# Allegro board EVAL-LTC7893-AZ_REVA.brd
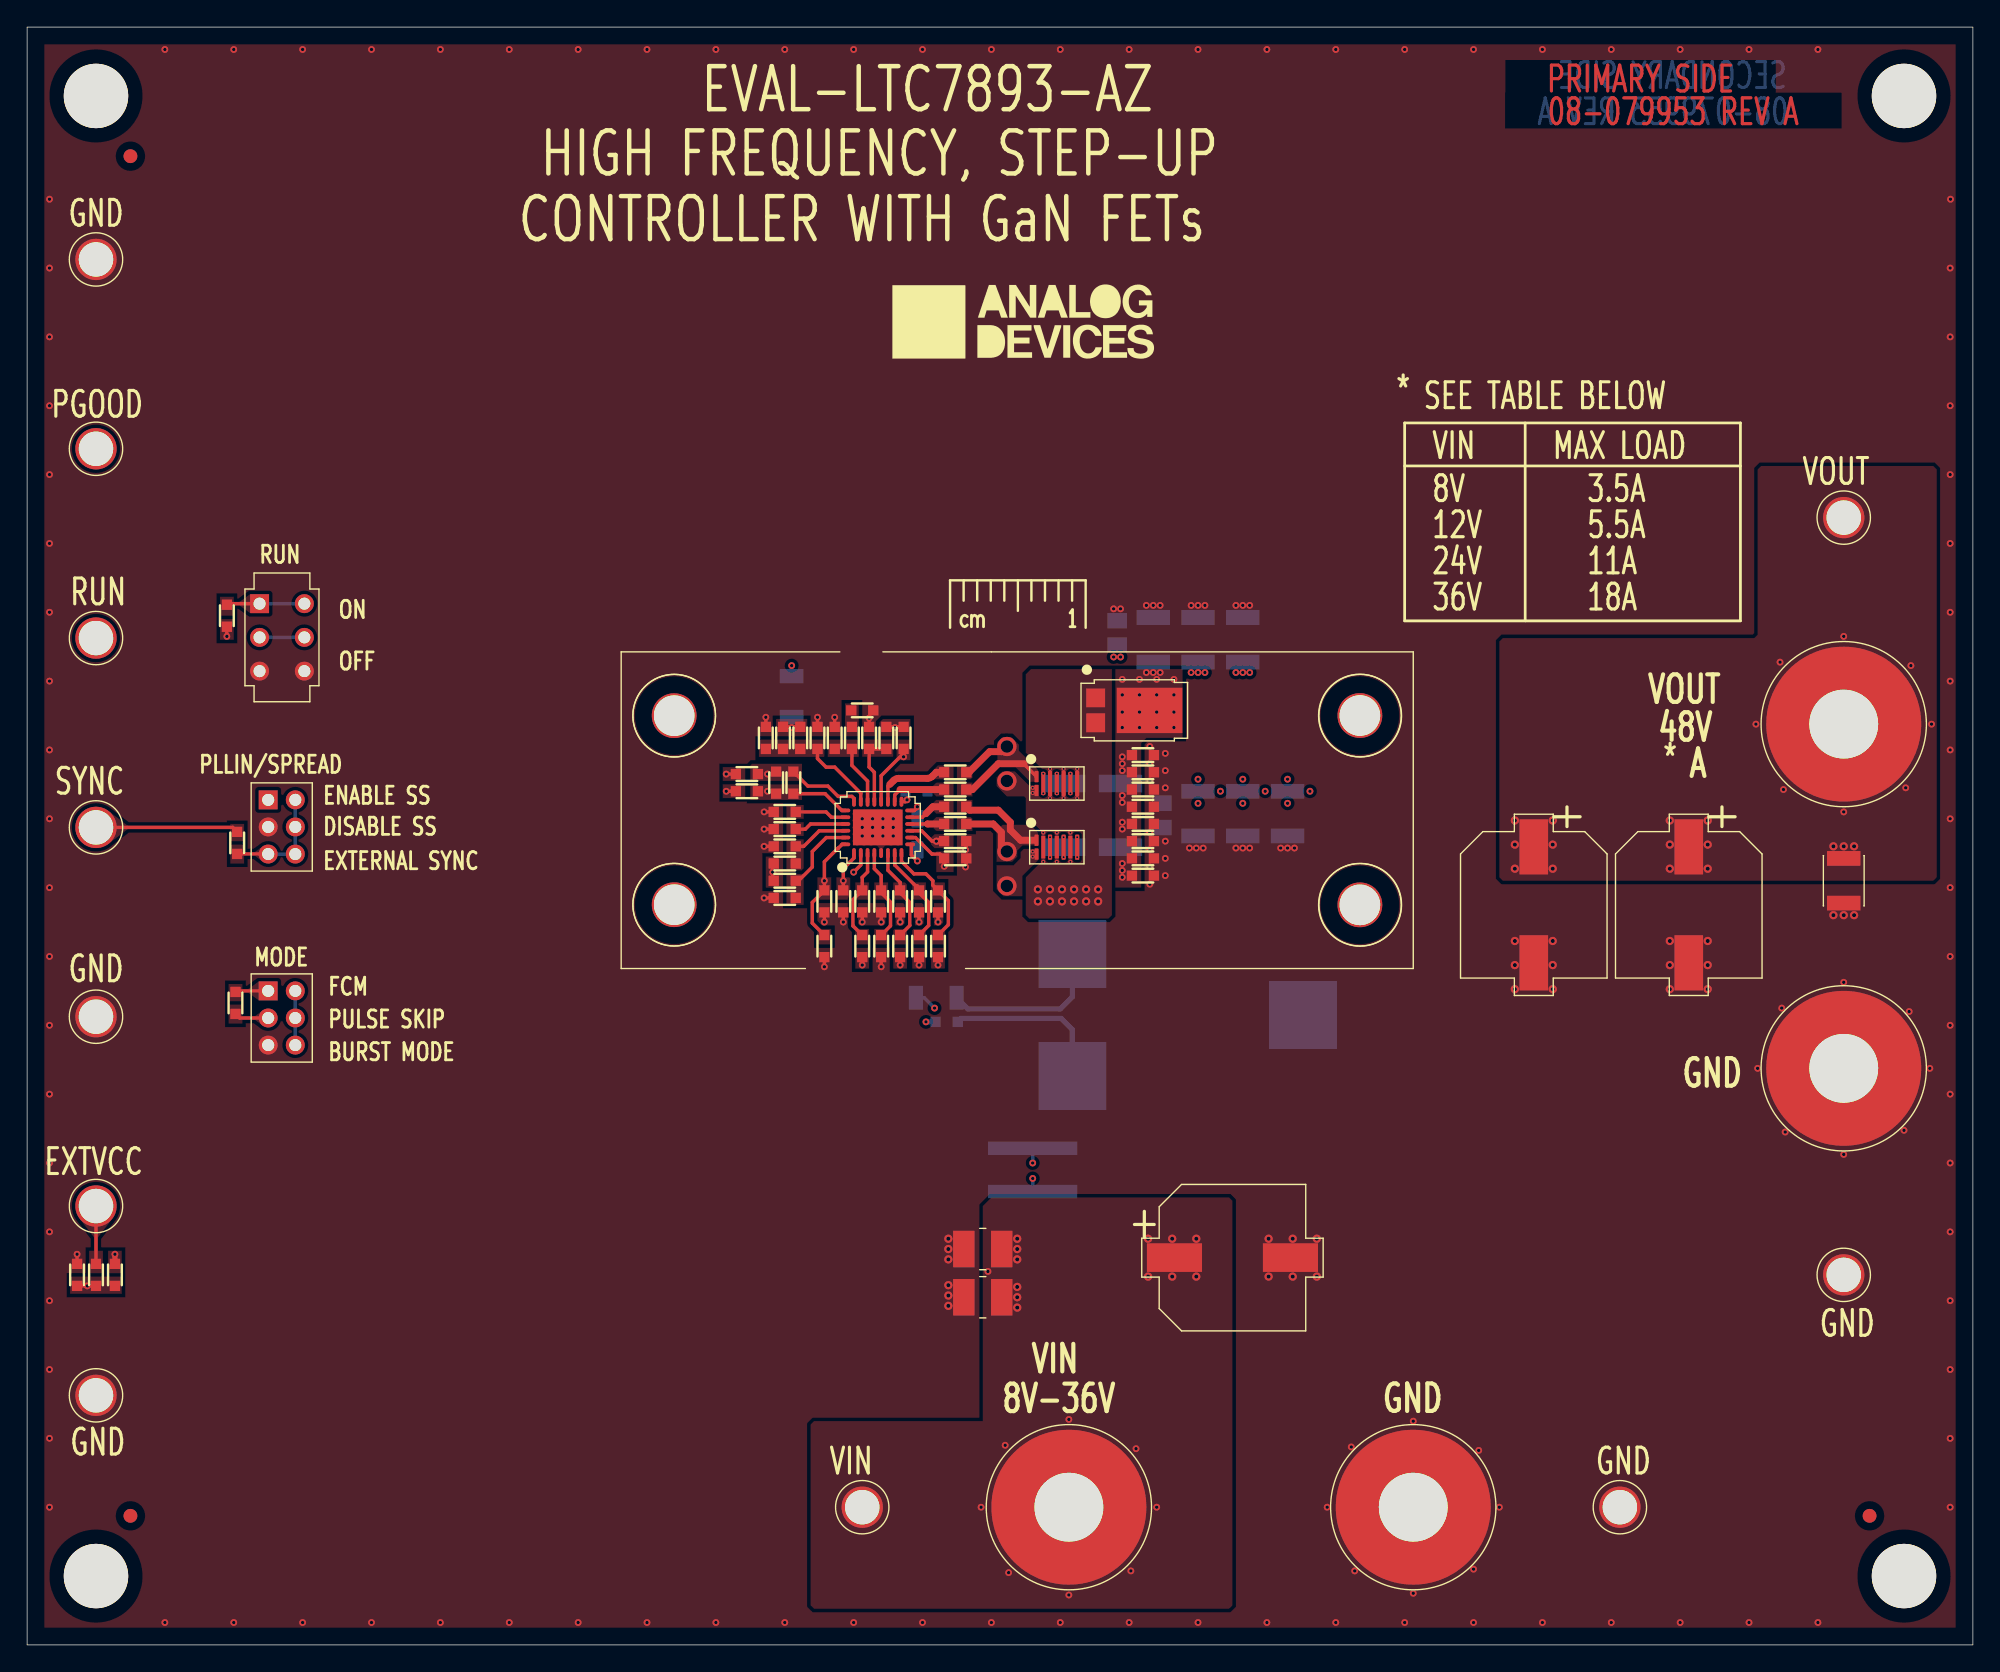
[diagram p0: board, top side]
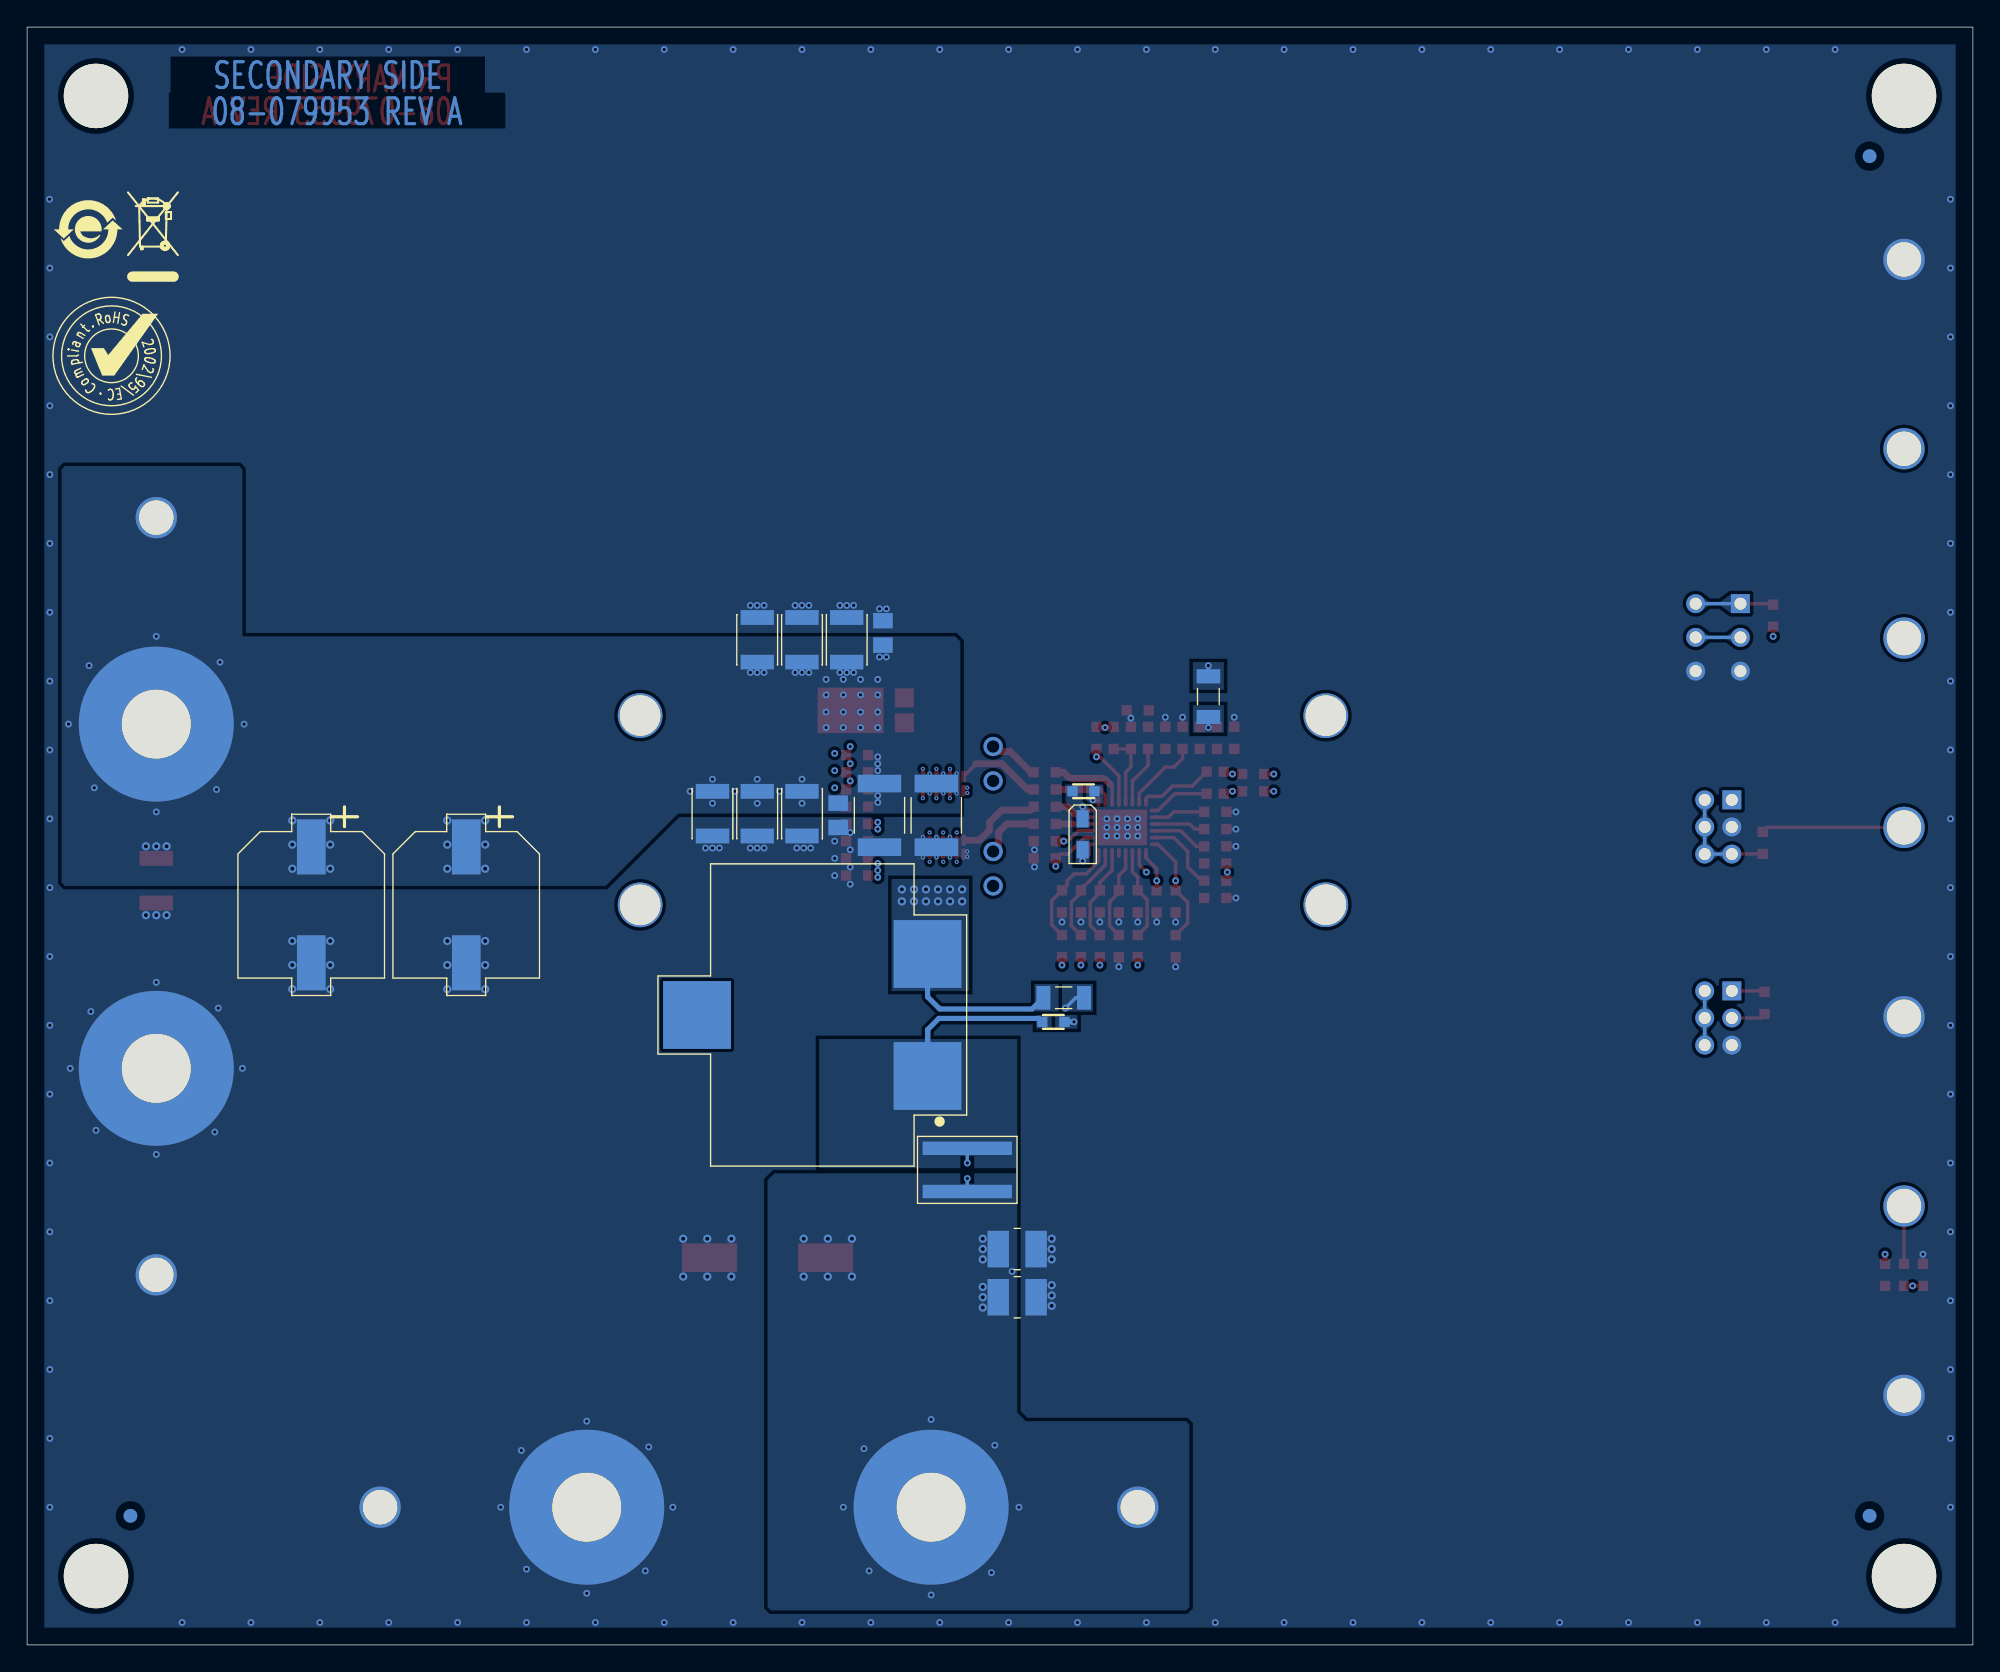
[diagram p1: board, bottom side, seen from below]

Outline 143.51 x 119.38 mm; copper layers: TOP, LAYER_2, LAYER_3, LAYER_4, LAYER_5, BOTTOM. Coordinates in mm from the lower left corner of the outline.
Outline path: 0,119.38 0,0 143.51,0 143.51,119.38 0,119.38

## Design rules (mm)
constraint set DEFAULT: min track width 0.254

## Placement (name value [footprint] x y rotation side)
C1  TBD0603  [C0603]  57.02 66.93 270 top
C2  TBD0603  [C0603]  58.29 66.93 90 top
C3  TBD0603  [C0603]  60.2 54.86 270 top
C4  0.022uF  [C0603]  60.83 66.93 90 top
C5  0.1uF  [C0603]  62.99 54.86 270 top
C6  220pF  [C0603]  59.56 66.93 90 top
C7  0.1uF  [C0603]  65.79 54.86 270 top
C8  100PF  [C0603]  58.8 54.86 270 top
C9  1uF  [C0603]  68.45 58.04 0 top
C10  0.1uF  [C0603]  67.18 54.86 270 top
C11  4.7UF  [C0603]  68.45 59.31 0 top
C12  0.01uF  [C0603]  56.52 63.63 90 top
C13  0.1uF  [C0603]  65.6 62.99 180 bottom
C14  4.7UF  [C1812H110]  80.64 61.21 270 bottom
C15  4.7UF  [C1812H110]  76.45 61.21 270 bottom
C16  4.7uF  [C1210H87]  89.66 74.17 90 bottom
C17  4.7uF  [C1210H87]  86.36 74.17 90 bottom
C18  100UF  [CPLSMSQ406H508]  111.12 54.61 270 top
C19  100UF  [CPLSMSQ406H508]  122.56 54.61 270 top
C20  1UF  [C0805H55]  80.39 74.68 90 bottom
C21  1UF  [C0805H55]  83.69 61.21 270 bottom
C22  4.7uF  [C1210H87]  83.06 74.17 90 bottom
C23  4.7uF  [C1210H87]  92.96 61.34 270 bottom
C24  4.7uF  [C1210H87]  86.36 61.34 270 bottom
C25  4.7uF  [C1210H87]  89.66 61.34 270 bottom
C26  10uF  [C1210-2]  70.48 25.65 180 top
C27  4.7uF  [C1210H87]  133.99 56.39 270 top
C28  100UF  [CPLSMSQ406H508]  111.12 54.61 270 bottom
C29  10uF  [C1210-2]  70.48 29.21 180 top
C30  10uF  [C1210-2]  70.48 29.21 180 bottom
C31  10uF  [C1210-2]  70.48 25.65 180 bottom
C32  100UF  [CPLSMSQ406H508]  122.56 54.61 270 bottom
C33  100UF  [CPLSMSQ406H508]  88.9 28.57 0 top
C34  0.22UF  [C0603]  82.3 65.66 0 top
C35  0.22UF  [C0603]  82.3 64.39 0 top
C36  0.22UF  [C0603]  82.3 63.12 0 top
C37  0.22UF  [C0603]  82.3 61.85 0 top
C38  0.22UF  [C0603]  82.3 60.58 0 top
C39  0.22UF  [C0603]  82.3 59.31 0 top
C40  0.22UF  [C0603]  82.3 58.04 0 top
C41  0.22UF  [C0603]  82.3 56.77 0 top
D1  BAT42WS-7-F  [SOD323]  65.66 59.82 270 bottom
D2  MBR5U100-TP  [TO227]  81.66 68.96 0 top
J1  CKFH1032-10  [CNCFCKFH1032-10]  76.83 10.16 0 top
J2  CKFH1032-10  [CNCFCKFH1032-10]  102.23 10.16 0 top
J3  CKFH1032-10  [CNCFCKFH1032-10]  133.99 67.94 0 top
J4  CKFH1032-10  [CNCFCKFH1032-10]  133.99 42.55 0 top
JP1  62000621121  [CNTHMHDR2X3L236W157H248]  17.78 48.26 270 top
JP2  62000621121  [CNTHMHDR2X3L236W157H248]  17.78 62.36 270 top
L1  3.1UH  [LSML858W571H571]  85.6 46.48 90 bottom
NOREF  -  []  -76.2 -76.2 0 top
NOREF#2  -  []  -76.2 -76.2 0 top
NOREF#3  VAL  []  73.03 61.59 0 top
NOREF#4  -  []  238.7 41.21 0 top
NOREF#5  -  []  124.26 115.57 270 top
NOREF#6  -  []  0 119.38 0 top
NOREF#7  -  [unnamed#2]  138.43 114.3 180 top
NOREF#8  -  [unnamed#2]  7.62 109.86 0 top
NOREF#9  -  []  68.07 75.06 0 top
NOREF#10  -  [unnamed#2]  5.08 5.08 180 top
NOREF#11  -  []  63.5 0 90 top
NOREF#12  -  []  -222.25 -146.05 0 top
NOREF#13  -  [unnamed#2]  5.08 114.3 180 top
NOREF#14  -  []  73.41 96.27 0 top
NOREF#15  -  [unnamed#2]  135.89 9.53 0 top
NOREF#16  -  []  143.51 0 90 top
NOREF#17  -  []  244.35 286 0 top
NOREF#18  -  [unnamed#2]  7.62 9.53 0 top
NOREF#19  -  []  78.8 71.12 0 top
NOREF#20  -  []  249.05 252.09 0 top
NOREF#21  -  []  -76.2 -76.2 0 top
NOREF#22  -  []  0 63.5 270 top
NOREF#23  -  []  294.96 220.28 0 top
NOREF#24  -  []  76.2 125.73 0 top
NOREF#25  -  [unnamed#2]  138.43 5.08 180 top
NOREF#26  -  []  -222.25 -146.05 0 top
NOREF#27  -  []  0 0 0 top
NOREF#28  -  []  63.5 63.5 180 top
NOREF#29  -  []  269.18 136.97 0 top
NOREF#30  -  []  134.43 100.65 180 bottom
NOREF#31  -  [unnamed#2]  7.62 109.86 180 bottom
NOREF#32  -  []  137.29 95.12 180 bottom
NOREF#33  -  [unnamed#2]  7.62 9.53 180 bottom
NOREF#34  -  []  139 104.46 180 bottom
NOREF#35  -  [unnamed#2]  135.89 9.53 180 bottom
P1  9774010243R  [CNWURTH9774010243R]  47.73 68.57 0 top
P2  9774010243R  [CNWURTH9774010243R]  47.73 54.62 0 top
P3  9774010243R  [CNWURTH9774010243R]  98.3 68.58 0 top
P4  9774010243R  [CNWURTH9774010243R]  98.3 54.61 0 top
Q1  EPC2088  [DIE8_3_5X1_95_A]  75.95 63.56 0 top
Q2  EPC2088  [DIE8_3_5X1_95_A]  75.95 58.86 0 top
R1  475K  [R0603]  55.75 66.93 270 top
R2  12.1K  [R0603]  54.48 66.93 90 top
R3  1K  [R0603]  15.49 59.18 270 top
R4  TBD0603  [R0603]  5.08 27.3 270 top
R5  TBD0603  [R0603]  62.99 51.56 270 top
R6  0  [R0603]  3.68 27.3 90 top
R7  10K  [R0603]  61.59 68.96 0 top
R8  1MEG  [R0603]  14.73 75.95 90 top
R9  1MEG  [R0603]  64.64 66.93 270 top
R10  100K  [R0603]  15.37 47.37 270 top
R11  187K  [R0603]  58.8 51.56 270 top
R12  TBD0603  [R0603]  61.59 51.56 90 top
R13  73.2K  [R0603]  61.59 54.86 90 top
R14  0  [R0603]  65.79 51.56 90 top
R15  0  [R0603]  63.37 66.93 270 top
R16  TBD0603  [R0603]  62.1 66.93 270 top
R17  TBD0603  [R0603]  55.88 57.66 0 top
R18  0  [R0603]  55.88 58.93 180 top
R19  0  [R0603]  67.18 51.56 90 top
R20  1  [R0603]  68.45 64.39 0 top
R21  1  [R0603]  68.45 63.12 0 top
R22  2.2  [R0603]  68.45 60.58 0 top
R23  1  [R0603]  68.45 61.85 0 top
R24  24.9K  [R0603]  55.88 60.2 180 top
R25  10K  [R0603]  55.88 61.47 180 top
R26  TBD0603  [R0603]  64.39 51.56 270 top
R27  TBD0603  [R0603]  64.39 54.86 270 top
R28  TBD0603  [R0603]  55.24 63.63 90 top
R29  TBD0603  [R0603]  55.88 56.39 180 top
R30  TBD0603  [R0603]  55.88 55.12 180 top
R31  TBD1206  [R1206]  67.06 47.75 180 bottom
R32  TBD0603  [R0603]  67.82 45.97 180 bottom
R33  1  [R0603]  53.09 64.26 0 top
R34  0.002  [R1225H28]  74.17 35.05 270 bottom
R35  TBD0603  [R0603]  6.48 27.3 90 top
R36  0  [R0603]  53.09 62.99 0 top
R37  10  [R1206]  56.39 69.98 90 bottom
S1  JS202011CQN  [SWTHL354W142H217]  17.14 76.83 270 top
TP1  2501-2-00-80-00-00-07-0  [CNMILLMAX2501]  5.08 74.3 0 top
TP2  2501-2-00-80-00-00-07-0  [CNMILLMAX2501]  5.08 88.27 0 top
TP3  2501-2-00-80-00-00-07-0  [CNMILLMAX2501]  5.08 60.33 0 top
TP4  2501-2-00-80-00-00-07-0  [CNMILLMAX2501]  5.08 32.38 0 top
TP5  2501-2-00-80-00-00-07-0  [CNMILLMAX2501]  5.08 46.35 0 top
TP6  2501-2-00-80-00-00-07-0  [CNMILLMAX2501]  5.08 102.23 0 top
TP7  2501-2-00-80-00-00-07-0  [CNMILLMAX2501]  133.99 83.19 0 top
TP10  2501-2-00-80-00-00-07-0  [CNMILLMAX2501]  133.99 27.3 0 top
TP11  2501-2-00-80-00-00-07-0  [CNMILLMAX2501]  61.59 10.16 0 top
TP14  2501-2-00-80-00-00-07-0  [CNMILLMAX2501]  117.47 10.16 0 top
TP15  2501-2-00-80-00-00-07-0  [CNMILLMAX2501]  5.08 18.41 0 top
U1  LTC7893AUFDM#PBF  [QFN28_5X4_PAD3_65X2_65_05-08-1682]  62.74 60.33 0 top

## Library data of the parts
C1-C3 = CAP: User Part Number: UPN; alternate symbols: (C0603); part number: CAP_SM-TBD0603,TBD0603,TBD0603,E000382,C0603
C4 = CAP: Tolerance: 10; User Part Number: UPN; alternate symbols: (C0603); part number: CAP_SM-0.022UF,50V,10,E015725,C0603; tolerance: 10
C5 C10 C13 = CAP: Tolerance: 10; User Part Number: UPN; alternate symbols: (C0603); part number: CAP_SM-0.1UF,25V,10,E013746,C0603; tolerance: 10
C6 = CAP: Tolerance: 5; User Part Number: UPN; alternate symbols: (C0603); part number: CAP_SM-220PF,50V,5,E000417,C0603; tolerance: 5
C7 = CAP: Tolerance: 10; User Part Number: UPN; alternate symbols: (C0603); part number: CAP_SM-0.1UF,100V,10,E024908,C0603; tolerance: 10
C8 = CAP: Tolerance: 10; User Part Number: UPN; alternate symbols: (C0603); part number: CAP_SM-100PF,25V,10,E062855,C0603; tolerance: 10
C9 = CAP: Tolerance: 10; User Part Number: UPN; alternate symbols: (C0603); part number: CAP_SM-1UF,25V,10,E033832,C0603; tolerance: 10
C11 = CAP: Tolerance: 10; User Part Number: UPN; alternate symbols: (C0603); part number: CAP_SM-4.7UF,25V,10,E058970,C0603; tolerance: 10
C12 = CAP: Tolerance: 10; User Part Number: UPN; alternate symbols: (C0603); part number: CAP_SM-0.01UF,50V,10,E018587,C0603; tolerance: 10
C14 C15 = CAP: User Part Number: UPN; Tolerance: 10; alternate symbols: (C1812H110); part number: CAP_SM-4.7UF,100V,10,E063338,C1812H110; tolerance: 10
C16 C17 C22-C25 C27 = CAP: Tolerance: 10; User Part Number: UPN; alternate symbols: (C1210H87); part number: CAP_SM-4.7UF,100V,10,E033812,C1210H87; tolerance: 10
C18 C19 C28 C32 C33 = CAPP: User Part Number: UPN; Tolerance: 20; alternate symbols: (CPLSMSQ406H508); part number: CAPP_SM-100UF,63V,20,E067384,CPLSMSQ406H508; tolerance: 20
C20 C21 = CAP: User Part Number: UPN; Tolerance: 10; alternate symbols: (C0805H55); part number: CAP_SM-1UF,100V,10,E048499,C0805H55; tolerance: 10
C26 C29-C31 = CAP: Tolerance: 10; User Part Number: UPN; alternate symbols: (C1210-2); part number: CAP_SM-10UF,50V,10,E022361,C1210-2; tolerance: 10
C34-C41 = CAP: Tolerance: 10; User Part Number: UPN; alternate symbols: (C0603); part number: CAP_SM-0.22UF,100V,10,E061685,C0603; tolerance: 10
D1 = DIOSCHOTTKY: Tolerance: N/A; User Part Number: UPN; alternate symbols: (SOD323); part number: DIOSCHOTTKY_SM-BAT42WS-7-F,30V,N/A,E033361,SOD323; tolerance: N/A
D2 = DIOSCHOTTKY_3P: User Part Number: UPN; Tolerance: N/A; alternate symbols: (TO227); part number: DIOSCHOTTKY_3P_SM-MBR5U100-TP,100V,N/A,E067592,TO227; tolerance: N/A
J1-J4 = CNTP1P: Tolerance: N/A; User Part Number: UPN; alternate symbols: (CNCFCKFH1032-10_C450D200); part number: CNTP1P_TH-CKFH1032-10,E050511,CNCFCKFH1032-10; tolerance: N/A
JP1 JP2 = CN6P_ODD_EVEN: User Part Number: UPN; Tolerance: N/A; alternate symbols: (CNTHMHDR2X3L236W157H248); part number: CN6P_ODD_EVEN_SM-62000621121,E035206,CNTHMHDR2X3L236W157H248; tolerance: N/A
L1 = IND: Tolerance: 15; User Part Number: UPN; alternate symbols: (LSML858W571H571); part number: IND_SM-3.1UH,15,E067382,LSML858W571H571; tolerance: 15
NOREF#3 = -: User Part Number: UPN; Tolerance: TOL
P1-P4 = CN1P: Tolerance: N/A; User Part Number: UPN; alternate symbols: (CNWURTH9774010243R); part number: CN1P_TH-9774010243R,E060235,CNWURTH9774010243R; tolerance: N/A
Q1 Q2 = TRANNGANFET8P: Tolerance: www.epc-co.com; User Part Number: UPN; alternate symbols: (DIE8_3_5X1_95_A); part number: TRANNGANFET8P_SM-EPC2088,E063004,DIE8_3_5X1_95_A; tolerance: www.epc-co.com
R1 = RES: Tolerance: 1; User Part Number: UPN; alternate symbols: (R0603); part number: RES_SM-475K,E032846,1/10W,1,R0603; tolerance: 1
R2 = RES: Tolerance: 1; User Part Number: UPN; alternate symbols: (R0603); part number: RES_SM-12.1K,E003741,1/10W,1,R0603; tolerance: 1
R3 = RES: Tolerance: 1; User Part Number: UPN; alternate symbols: (R0603); part number: RES_SM-1K,E003678,1/10W,1,R0603; tolerance: 1
R4 R5 R12 R16 R17 R26-R30 R32 R35 = RES: User Part Number: UPN; alternate symbols: (R0603); part number: RES_SM-TBD0603,E004050,TBD0603,TBD0603,R0603
R6 R14 R15 R18 R19 R36 = RES: Tolerance: JUMPER; User Part Number: UPN; alternate symbols: (R0603); part number: RES_SM-0,E006826,1/10W,JUMPER,R0603; tolerance: JUMPER
R7 R25 = RES: Tolerance: 1; User Part Number: UPN; alternate symbols: (R0603); part number: RES_SM-10K,E003671,1/10W,1,R0603; tolerance: 1
R8 R9 = RES: Tolerance: 1; User Part Number: UPN; alternate symbols: (R0603); part number: RES_SM-1MEG,E003682,1/10W,1,R0603; tolerance: 1
R10 = RES: Tolerance: 1; User Part Number: UPN; alternate symbols: (R0603); part number: RES_SM-100K,E010279,1/10W,1,R0603; tolerance: 1
R11 = RES: Tolerance: 1; User Part Number: UPN; alternate symbols: (R0603); part number: RES_SM-187K,E057319,1/10W,1,R0603; tolerance: 1
R13 = RES: Tolerance: 1; User Part Number: UPN; alternate symbols: (R0603); part number: RES_SM-73.2K,E043106,1/10W,1,R0603; tolerance: 1
R20 R21 R23 R33 = RES: User Part Number: UPN; alternate symbols: (R0603); part number: RES_SM-1,E044403,1/10W,1,R0603
R22 = RES: Tolerance: 1; User Part Number: UPN; alternate symbols: (R0603); part number: RES_SM-2.2,E017481,1/10W,1,R0603; tolerance: 1
R24 = RES: Tolerance: 1; User Part Number: UPN; alternate symbols: (R0603); part number: RES_SM-24.9K,E030453,1/10W,1,R0603; tolerance: 1
R31 = RES: User Part Number: UPN; alternate symbols: (R1206); part number: RES_SM-TBD1206,E004052,TBD1206,TBD1206,R1206
R34 = RES: User Part Number: UPN; Tolerance: 2; alternate symbols: (R1225H28); part number: RES_SM-0.002,E046965,3W,2,R1225H28; tolerance: 2
R37 = RES: User Part Number: UPN; Tolerance: 1; alternate symbols: (R1206); part number: RES_SM-10,E003286,1/4W,1,R1206; tolerance: 1
S1 = SWDPDT_V5: Tolerance: N/A; User Part Number: UPN; alternate symbols: (SWTHL354W142H217); part number: SWDPDT_V5_TH-JS202011CQN,E025828,SWTHL354W142H217; tolerance: N/A
TP1-TP7 TP10 TP11 TP14 TP15 = CNTP1P: User Part Number: UPN; Tolerance: N/A; alternate symbols: (CNMILLMAX2501); part number: CNTP1P_TH-2501-2-00-80-00-00-07-0,E031108,CNMILLMAX2501; tolerance: N/A
U1 = ADILTC7893: User Part Number: UPN; Tolerance: N/A; alternate symbols: (QFN28_5X4_PAD3_65X2_65_05-08-1682); part number: ADILTC7893_SM-LTC7893AUFDM#PBF,E062848,QFN28_5X4_PAD3_65X2_65_05-08-1682; tolerance: N/A

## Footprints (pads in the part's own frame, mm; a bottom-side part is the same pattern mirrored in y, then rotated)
C0603
  rect 0.762x0.762 smd: 1(-0.813,0) 2(0.813,0)
C0805H55
  rect 1.143x1.448 smd: 1(-0.9,0) 2(0.9,0)
C1210-2
  rect 1.575x2.692 smd: 1(-1.397,0) 2(1.397,0)
C1210H87
  rect 1.092x2.464 smd: 1(-1.646,0) 2(1.646,0)
C1812H110
  rect 1.295x3.2 smd: 1(-2.348,0) 2(2.348,0)
CNCFCKFH1032-10
  round 11.43 hole 5.08: 1(0,0)
CNMILLMAX2501
  round 3.048 hole 2.54: 1(0,0)
CNTHMHDR2X3L236W157H248
  rect 1.397x1.397 hole 0.889: 1(0,0)
  round 1.397 hole 0.889: 2(0,2) 3(2,0) 4(2,2) 5(4,0) 6(4,2)
CNWURTH9774010243R
  round 3.302 hole 2.997 unplated: (0,0)
  round 0 smd: 1(0,0)
CPLSMSQ406H508
  rect 4.064x2.108 smd: N(4.277,0) P(-4.277,0)
DIE8_3_5X1_95_A
  rrect 0.305x0.838 smd: 1(-1.5,0.513) 2(-1.5,-0.513)
  rrect 0.305x1.676 smd: 3(-1,0) 5(0,0) 7(1,0)
  rrect 0.305x1.854 smd: 4(-0.5,0) 6(0.5,0) 8(1.5,0)
LSML858W571H571
  rect 5.004x5.004 smd: (0,8.502) 1(-4.502,-8.502) 2(4.502,-8.502)
QFN28_5X4_PAD3_65X2_65_05-08-1682
  oval 0.279x0.737 smd: 1(-1.75,-1.893) 2(-1.25,-1.893) 3(-0.75,-1.893) 4(-0.25,-1.893) 5(0.25,-1.893) 6(0.75,-1.893) 7(1.25,-1.893) 8(1.75,-1.893) 15(1.75,1.893) 16(1.25,1.893) 17(0.75,1.893) 18(0.25,1.893) 19(-0.25,1.893) 20(-0.75,1.893) 21(-1.25,1.893) 22(-1.75,1.893)
  oval 0.737x0.279 smd: 9(2.393,-1.25) 10(2.393,-0.75) 11(2.393,-0.25) 12(2.393,0.25) 13(2.393,0.75) 14(2.393,1.25) 23(-2.393,1.25) 24(-2.393,0.75) 25(-2.393,0.25) 26(-2.393,-0.25) 27(-2.393,-0.75) 28(-2.393,-1.25)
  rect 3.658x2.642 smd: 29(0,0)
R0603
  rect 0.762x0.762 smd: 1(-0.813,0) 2(0.813,0)
R1206
  rect 1.041x1.753 smd: 1(-1.5,0) 2(1.5,0)
R1225H28
  rect 0.991x6.579 smd: 1(-1.595,0) 2(1.595,0)
SOD323
  rect 1.27x0.889 smd: A(1.143,0) C(-1.143,0)
SWTHL354W142H217
  rect 1.397x1.397 hole 0.889: 1(0,0)
  round 1.397 hole 0.889: 2(2.489,0) 3(4.978,0) 4(0,3.302) 5(2.489,3.302) 6(4.978,3.302)
TO227
  rect 1.397x1.397 smd: 1(-2.851,0.92) 2(-2.851,-0.92)
  rect 4.851x3.353 smd: 3(1.123,0)
unnamed#2
  round 4.75 hole 4.75 unplated: (0,0)

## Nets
GND_SIGNAL: C2.2(N2) C3.2(N2) C5.2(N2) C6.2(N2) C7.2(N2) C8.2(N2) C9.2(N2) C10.2(N2) C11.2(N2) C14.2(N2) C15.2(N2) C16.2(N2) C17.2(N2) C18.N(N2) C19.N(N2) C20.2(N2) C21.2(N2) C22.2(N2) C23.2(N2) C24.2(N2) C25.2(N2) C26.2(N2) C27.2(N2) C28.N(N2) C29.2(N2) C30.2(N2) C31.2(N2) C32.N(N2) C33.N(N2) C34.2(N2) C35.2(N2) C36.2(N2) C37.2(N2) C38.2(N2) C39.2(N2) C40.2(N2) C41.2(N2) J2.1(N1) J4.1(N1) JP1.5 JP2.3 Q2.2 Q2.4 Q2.6 Q2.8(S4) R2.2(N2) R5.2(N2) R6.2(N2) R7.2(N2) R11.2(N2) R13.1 R16.1 R18.2(N2) R24.2(N2) R25.2(N2) R27.2(N2) R30.2(N2) S1.3 S1.6(NO2) TP5.1(N1) TP6.1(N1) TP10.1(N1) TP14.1(N1) TP15.1(N1) U1.5 U1.29
VIN: C26.1 C29.1 C30.1 C31.1 C33.P J1.1(N1) R8.1 R14.1 R34.2(N2) R36.1 TP11.1(N1)
BG: Q2.1 R22.2(N2) R23.2(N2)
BOOST: C13.1 D1.C U1.14
EXTVCC: C9.1 R4.2(N2) R6.1 R35.1 U1.10
INTVCC: C11.1 JP1.1 JP2.1 R9.1 R10.1 R12.1 R15.1 R17.1 R19.1 R26.2(N2) R29.2(N2) U1.11
SENSE+: C12.1 R28.1 R32.2(N2) R36.2(N2) U1.23
SENSE-: C12.2(N2) R28.2(N2) R31.2(N2) R33.2(N2) U1.22
SW: C13.2(N2) D2.1 D2.2 L1.2(N2) Q1.2 Q1.4 Q1.6 Q1.8(S4) Q2.3 Q2.5 Q2.7 R31.1 U1.15
TG: Q1.1 R20.2(N2) R21.2(N2)
UNNAMED_2_ADILTC7893_I41_BGDN: R23.1 U1.13
UNNAMED_2_ADILTC7893_I41_BGUP: R22.1 U1.12
UNNAMED_2_ADILTC7893_I41_BSTVCC: D1.A(P) U1.9
UNNAMED_2_ADILTC7893_I41_DRVCC: C10.1 R19.2(N2) U1.8
UNNAMED_2_ADILTC7893_I41_DRVSET: R17.2(N2) R18.1 U1.26
UNNAMED_2_ADILTC7893_I41_DRVUV: R29.1 R30.1 U1.27
UNNAMED_2_ADILTC7893_I41_DTCA: R24.1 U1.25
UNNAMED_2_ADILTC7893_I41_DTCB: R25.1 U1.24
UNNAMED_2_ADILTC7893_I41_FREQ: R12.2(N2) R13.2(N2) U1.3
UNNAMED_2_ADILTC7893_I41_ILIM: R15.2(N2) R16.2(N2) U1.19
UNNAMED_2_ADILTC7893_I41_ITH: C4.1 C6.1 U1.20
UNNAMED_2_ADILTC7893_I41_MODE: JP1.2 JP1.4 JP1.6(N6) U1.2
UNNAMED_2_ADILTC7893_I41_PGOOD: R9.2(N2) TP2.1(N1) U1.18
UNNAMED_2_ADILTC7893_I41_PLLIN: C3.1 JP2.2 JP2.4 JP2.5 JP2.6(N6) R3.2(N2) U1.1
UNNAMED_2_ADILTC7893_I41_RUN: C8.1 R11.1 S1.2 S1.5 TP1.1(N1) U1.28
UNNAMED_2_ADILTC7893_I41_SS: C5.1 R5.1 U1.4
UNNAMED_2_ADILTC7893_I41_TGDN: R21.1 U1.16
UNNAMED_2_ADILTC7893_I41_TGUP: R20.1 U1.17
UNNAMED_2_ADILTC7893_I41_VBIAS: C7.1 R14.2(N2) U1.7
UNNAMED_2_ADILTC7893_I41_VFB: C1.2(N2) C2.1 R1.2(N2) R2.1 U1.21
UNNAMED_2_ADILTC7893_I41_VPRG: R26.1 R27.1 U1.6(VPRG)
UNNAMED_2_CAP_I18_N2: C4.2(N2) R7.1
UNNAMED_2_CN6PODDEVEN_I38_N3: JP1.3 R10.2(N2)
UNNAMED_2_CNTP1P_I3_N1: R3.1 TP3.1(N1)
UNNAMED_2_CNTP1P_I33_N1: R4.1 TP4.1(N1)
UNNAMED_2_IND_I124_N1: L1.1 R32.1 R33.1 R34.1
UNNAMED_2_RES_I30_N2: R8.2(N2) S1.1 S1.4
VOUT: C14.1 C15.1 C16.1 C17.1 C18.P C19.P C20.1 C21.1 C22.1 C23.1 C24.1 C25.1 C27.1 C28.P C32.P C34.1 C35.1 C36.1 C37.1 C38.1 C39.1 C40.1 C41.1 D2.3(C) J3.1(N1) Q1.3 Q1.5 Q1.7 R35.2(N2) R37.2(N2) TP7.1(N1)
VSOP: C1.1 R1.1 R37.1

Pads without a net: P1 1; P2 1; P3 1; P4 1

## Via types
v1: diameter 0.508, hole 0.254, TOP to BOTTOM, 262 vias
v2: diameter 0.61, hole 0.305, TOP to BOTTOM, 66 vias
v3: diameter 0.305, hole 0.152, TOP to BOTTOM, 28 vias
v4: diameter 1.422, hole 0.927, TOP to BOTTOM, 4 vias

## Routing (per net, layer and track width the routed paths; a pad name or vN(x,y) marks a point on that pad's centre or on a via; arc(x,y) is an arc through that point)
GND_SIGNAL: length 14.1
  TOP w0.254: R25.2 v1(54.36,61.47) ; C3.2 v1(60.2,53.34) ; R24.2 v1(54.36,60.2) ; C5.2 v1(62.99,53.34) ; R13.1 v1(61.59,53.34) ; R6.2 v1(3.68,28.83) ; R27.2 v1(64.39,53.34) ; C2.2 v1(58.29,68.45) ; R16.1 v1(62.1,68.39) ; C8.2 v1(58.8,53.34) ; C10.2 v1(67.18,53.34) ; C9.2 69.27,57.45 v1(69.22,57.4) ; C7.2 v1(65.79,53.34) ; R18.2 v1(54.36,58.93) ; R11.2 v1(58.8,50.04) ; v1(69.22,58.67) 69.27,58.72 C11.2 ; C6.2 v1(59.56,68.45) ; R5.2 v1(62.99,50.04) ; R2.2 v1(54.48,68.45) ; R30.2 v1(54.36,55.12)
  vias: v1(1.65,106.68) v1(1.65,101.6) v1(1.65,96.52) v1(1.65,91.44) v1(1.65,86.36) v1(1.65,81.28) v1(1.65,76.2) v1(1.65,71.12) v1(1.65,66.04) v1(1.65,60.96) v1(1.65,55.88) v1(1.65,50.8) v1(1.65,45.72) v1(1.65,40.64) v1(1.65,35.56) v1(1.65,30.48) v1(1.65,25.4) v1(1.65,20.32) v1(1.65,15.24) v1(1.65,10.16) v1(10.16,117.73) v1(10.16,1.65) v1(15.24,117.73) v1(15.24,1.65) v1(20.32,117.73) v1(20.32,1.65) v1(25.4,117.73) v1(25.4,1.65) v1(30.48,117.73) v1(30.48,1.65) v1(35.56,117.73) v1(35.56,1.65) v1(40.64,117.73) v1(40.64,1.65) v1(45.72,117.73) v1(45.72,1.65) v1(50.8,117.73) v1(50.8,1.65) v1(55.88,117.73) v1(55.88,1.65) v1(60.96,117.73) v1(60.96,1.65) v1(61.59,60.96) v1(61.59,60.33) v1(61.59,59.69) v1(62.36,60.96) v1(62.36,60.33) v1(62.36,59.69) v1(63.12,60.96) v1(63.12,60.33) v1(63.12,59.69) v1(63.88,60.96) v1(63.88,60.33) v1(63.88,59.69) v1(66.04,117.73) v1(66.04,1.65) v1(71.12,117.73) v1(71.12,1.65) v1(76.2,117.73) v1(76.2,1.65) v1(80.14,76.45) v1(80.64,76.45) v1(81.28,117.73) v1(81.28,1.65) v1(82.55,76.71) v1(82.8,66.29) v1(82.8,65.02) v1(82.8,63.75) v1(82.8,59.94) v1(82.8,58.67) v1(82.8,57.4) v1(82.8,56.13) v1(83.06,76.71) v1(83.57,76.71) v1(83.95,65.79) v1(83.95,64.52) v1(83.95,63.25) v1(83.95,59.31) v1(83.95,58.04) v1(83.95,56.77) v1(85.72,58.8) v1(85.85,76.71) v1(86.23,58.8) v1(86.36,117.73) v1(86.36,76.71) v1(86.36,1.65) v1(86.74,58.8) v1(86.87,76.71) v1(89.15,76.71) v1(89.15,58.8) v1(89.66,76.71) v1(89.66,58.8) v1(90.17,76.71) v1(90.17,58.8) v1(91.44,117.73) v1(91.44,1.65) v1(92.46,58.8) v1(92.96,58.8) v1(93.47,58.8) v1(95.89,10.16) v1(96.52,117.73) v1(96.52,1.65) v1(97.66,14.61) v1(97.92,5.46) v1(101.6,117.73) v1(101.6,1.65) v1(102.23,16.51) v1(102.23,3.81) v1(106.68,117.73) v1(106.68,5.59) v1(106.68,1.65) v1(107.06,14.35) v1(108.58,10.16) v1(111.76,117.73) v1(111.76,1.65) v1(116.84,117.73) v1(116.84,1.65) v1(121.92,117.73) v1(121.92,1.65) v1(127,117.73) v1(127,1.65) v1(127.64,42.55) v1(129.41,46.99) v1(129.67,37.85) v1(132.08,117.73) v1(132.08,1.65) v1(133.99,48.9) v1(133.99,36.2) v1(138.43,37.97) v1(138.81,46.74) v1(140.34,42.55) v1(141.83,101.6) v1(141.83,96.52) v1(141.83,91.44) v1(141.83,86.36) v1(141.83,81.28) v1(141.83,76.2) v1(141.83,71.12) v1(141.83,66.04) v1(141.83,60.96) v1(141.83,55.88) v1(141.83,50.8) v1(141.83,45.72) v1(141.83,40.64) v1(141.83,35.56) v1(141.83,30.48) v1(141.83,25.4) v1(141.83,20.32) v1(141.83,15.24) v1(141.83,10.16) v1(141.86,106.68) v2(67.94,29.97) v2(67.94,29.21) v2(67.94,28.45) v2(67.94,26.54) v2(67.94,25.78) v2(67.94,25.02) v2(91.57,29.97) v2(91.57,27.18) v2(93.34,29.97) v2(93.34,27.18) v2(95.12,29.97) v2(95.12,27.18) v2(109.73,51.94) v2(109.73,50.16) v2(109.73,48.39) v2(112.52,51.94) v2(112.52,50.16) v2(112.52,48.39) v2(121.16,51.94) v2(121.16,50.16) v2(121.16,48.39) v2(123.95,51.94) v2(123.95,50.16) v2(123.95,48.39) v2(133.22,53.85) v2(133.99,53.85) v2(134.75,53.85) v3(74.17,58.55) v3(74.17,58.17) v3(75.45,59.6) v3(75.45,58.13) v3(76.45,59.6) v3(76.45,58.13) v3(77.45,59.6) v3(77.45,58.13) v4(72.26,56.01)
VIN: length 156.2
  TOP w0.254: R14.1 v1(65.79,50.16) ; R8.1 v1(14.73,74.42) ; R36.1 v1(51.56,62.99)
  LAYER_3 w0.381: v1(14.73,74.42) 14.73,73.15 13.72,72.14 13.72,42.29 15.94,40.07 61.28,40.07 63.37,37.97 ; 63.37,37.97 64.77,39.37 64.77,48.39 65.79,49.4 v1(65.79,50.16) ; 63.37,37.97 63.37,31.62 67.44,27.56 v1(70.87,27.56)
  LAYER_4 w0.254: v1(51.56,62.99) 51.94,62.61 51.94,52.32 63.25,41.02 66.21,41.02 72.56,34.67 73.91,34.67 v1(74.17,34.42)
  BOTTOM w0.254: R34.2 v1(74.17,34.42)
  vias: v1(70.36,10.16) v1(72.14,14.73) v1(72.39,5.33) v1(76.83,16.64) v1(76.83,3.68) v1(81.41,5.46) v1(81.79,14.48) v1(83.31,10.16) v2(73.03,29.97) v2(73.03,29.21) v2(73.03,28.45) v2(73.03,26.42) v2(73.03,25.65) v2(73.03,24.89) v2(82.68,29.97) v2(82.68,27.18) v2(84.45,29.97) v2(84.45,27.18) v2(86.23,29.97) v2(86.23,27.18)
BG: length 11
  TOP w0.254: 74.3,59.38 Q2.1
  TOP w0.508: 74.3,59.38 73.27,59.38 72.52,60.13 72.52,60.71 71.63,61.59 69.52,61.59 R23.2 ; R22.2 71.25,60.58 71.86,59.97 71.86,58.95 v4(72.26,58.55)
BOOST: length 0.7
  TOP w0.254: v1(65.66,61.85) 65.66,61.79 65.45,61.57 U1.14
EXTVCC: length 108.5
  TOP w0.254: R6.1 v1(4.45,26.49) R4.2 ; v1(67.64,57.45) C9.1 67.32,58.36 66.74,58.36 65.52,59.57 U1.10
  LAYER_4 w0.254: v1(4.45,26.49) 4.45,28.83 5.65,30.04 63.18,30.04 65.79,32.64 74.8,32.64 76.39,34.23 76.39,43.62 70.55,49.47 70.55,54.55 v1(67.64,57.45)
INTVCC: length 120.6
  TOP w0.254: 64.06,67.74 R9.1 ; 64.06,67.74 v1(64.01,67.69) ; 64.06,67.74 R15.1 ; U1.11 65.97,60.08 66.74,59.31 v1(67.06,59.31) ; v1(67.18,50.16) R19.1 ; JP1.1 15.44,48.26 R10.1 ; R26.2 v1(64.39,50.16) ; R17.1 54.99,57.58 v1(54.99,57.02) 54.99,56.46 R29.2 ; R12.1 v1(61.59,50.16)
  TOP w0.508: C11.1 v1(67.06,59.31)
  LAYER_3 w0.254: v1(67.18,50.16) 67.18,50.55 66.42,51.31 64.39,51.31 ; v1(64.39,50.16) 64.39,51.31 ; 64.39,51.31 62.36,51.31 61.59,50.55 v1(61.59,50.16) 61.59,46.86 57.02,42.29 16.76,42.29 15.88,43.18 15.88,46.35 JP1.1 16,50.04 16,60.58 JP2.1
  LAYER_4 w0.254: v1(54.99,57.02) 54.99,55.24 60.07,50.16 v1(61.59,50.16) ; v1(64.01,67.69) 64.39,67.69 67.06,65.02 v1(67.06,59.31) 66.67,58.93 66.67,57.09 66.42,56.83 66.42,52.7 67.18,51.94 v1(67.18,50.16)
SENSE+: length 32.5
  TOP w0.254: v1(54.61,62.99) 55.07,62.99 R28.1 ; U1.23 60.09,61.57 58.85,62.81 C12.1
  LAYER_3 w0.254: v1(66.29,45.97) 66.29,47.5 68.71,49.91 68.71,53.34 67.18,54.86 65.15,54.86 61.59,58.42 60.33,58.42 55.37,63.37 54.99,63.37 v1(54.61,62.99)
  BOTTOM w0.381: R32.2 v1(66.29,45.97)
SENSE-: length 34.5
  TOP w0.254: C12.2 57.58,63.37 59.05,63.37 59.82,62.61 60.83,62.61 60.99,62.46 U1.22 ; v1(54.61,64.26) 55.07,64.26 R28.2
  LAYER_3 w0.254: v1(66.93,46.99) 66.93,47.37 69.22,49.66 69.22,53.59 67.44,55.37 65.42,55.37 61.91,58.88 61.9,58.88 61.85,58.93 60.58,58.93 55.63,63.88 54.99,63.88 v1(54.61,64.26)
  BOTTOM w0.254: R31.2 66.17,47.75 v1(66.93,46.99)
SW: length 12.9
  TOP w0.254: U1.15 64.76,62.22 v1(64.9,62.36)
  BOTTOM w0.381: L1.2 77.1,47.82 76.2,46.93 69.38,46.93 R31.1
  vias: v2(74.55,55.75) v2(74.55,54.86) v2(75.44,55.75) v2(75.44,54.86) v2(76.33,55.75) v2(76.33,54.86) v2(77.22,55.75) v2(77.22,54.86) v2(78.11,55.75) v2(78.11,54.86) v2(78.99,55.75) v2(78.99,54.86) v3(74.17,63.25) v3(74.17,62.87) v3(74.95,59.94) v3(74.95,57.78) v3(75.45,64.64) v3(75.45,62.48) v3(75.95,59.94) v3(75.95,57.78) v3(76.45,64.64) v3(76.45,62.48) v3(76.95,59.94) v3(76.95,57.78) v3(77.45,64.64) v3(77.45,62.48) v4(72.26,63.75)
TG: length 10.2
  TOP w0.254: Q1.1 73.53,64.99 73.53,65.02
  TOP w0.508: 73.53,65.02 71.63,65.02 69.72,63.12 R21.2 ; v4(72.26,66.29) 71.88,65.91 70.99,65.91 69.47,64.39 R20.2
UNNAMED_2_ADILTC7893_I41_BGDN: length 2.8
  TOP w0.254: U1.13 66.03,61.08 66.29,61.34
  TOP w0.508: 66.29,61.34 66.8,61.85 R23.1
UNNAMED_2_ADILTC7893_I41_BGUP: length 2.5
  TOP w0.254: U1.12 66.42,60.57
  TOP w0.508: R22.1 66.43,60.58 66.42,60.57
UNNAMED_2_ADILTC7893_I41_BSTVCC: length 1.4
  TOP w0.254: v1(65.66,57.85) 65.21,58.29 65.21,58.99 U1.9
UNNAMED_2_ADILTC7893_I41_DRVCC: length 8.3
  TOP w0.254: R19.2 67.94,53.14 67.94,54.91 C10.1 66.8,56.06 66.8,56.39 66.29,56.9 65.41,56.9 64.49,57.81 U1.8
UNNAMED_2_ADILTC7893_I41_DRVSET: length 4.1
  TOP w0.254: R18.1 57.28,58.93 58.42,60.08 U1.26
UNNAMED_2_ADILTC7893_I41_DRVUV: length 5.6
  TOP w0.254: U1.27 58.94,59.57 57.91,58.55 57.91,57.4 56.9,56.39 R29.1
UNNAMED_2_ADILTC7893_I41_DTCA: length 3.8
  TOP w0.254: U1.25 57.78,60.57 57.4,60.2 R24.1
UNNAMED_2_ADILTC7893_I41_DTCB: length 3.8
  TOP w0.254: U1.24 59.32,61.08 58.93,61.47 R25.1
UNNAMED_2_ADILTC7893_I41_FREQ: length 6.8
  TOP w0.254: U1.3 61.99,57.03 61.59,56.64 R13.2 60.91,54.99 60.91,53.06 R12.2
UNNAMED_2_ADILTC7893_I41_ILIM: length 5.3
  TOP w0.254: U1.19 62.49,64.39 62.1,64.77 R16.2 R15.2
UNNAMED_2_ADILTC7893_I41_ITH: length 4.4
  TOP w0.254: U1.20 61.99,63.74 60.83,64.9 C4.1
UNNAMED_2_ADILTC7893_I41_MODE: length 52.3
  TOP w0.254: v1(60.96,57.02) 61.49,57.55 U1.2
  LAYER_3 w0.254: JP1.2 54.86,48.26 59.5,52.9 59.5,53.78 61.34,55.63 61.34,56.64 v1(60.96,57.02)
  BOTTOM w0.254: JP1.6 JP1.4 JP1.2
UNNAMED_2_ADILTC7893_I41_PGOOD: length 73.8
  TOP w0.254: 64.64,65.79 62.99,64.13 U1.18 ; 64.64,65.79 v1(64.64,65.53) ; 64.64,65.79 R9.2
  LAYER_3 w0.254: TP2.1 19.05,88.27 35.43,71.88 49.66,71.88 51.31,70.23 58.93,70.23 63.63,65.53 v1(64.64,65.53)
UNNAMED_2_ADILTC7893_I41_PLLIN: length 53.9
  TOP w0.254: R3.2 17.77,58.37 JP2.5 ; U1.1 60.99,58.07 60.2,57.28 v1(60.2,56.39) C3.1
  LAYER_3 w0.254: v1(60.2,56.39) 60.2,55.88 59.56,55.24 58.29,55.24 55.24,58.29 19.84,58.29 JP2.6
  BOTTOM w0.254: JP2.5 JP2.6 JP2.4 JP2.2
UNNAMED_2_ADILTC7893_I41_RUN: length 70.7
  TOP w0.254: U1.28 60.12,59.08 59.84,58.8 59.81,58.8 58.8,57.78 v1(58.8,56.39) C8.1 57.91,54.79 57.91,53.26 R11.1
  LAYER_3 w0.254: S1.2 15.93,75.56 11.18,75.56 9.91,74.3 TP1.1 ; S1.5 33.96,60.83 54.86,60.83 58.8,56.9 v1(58.8,56.39)
  BOTTOM w0.254: S1.2 S1.5
UNNAMED_2_ADILTC7893_I41_SS: length 6.8
  TOP w0.254: U1.4 62.49,57.27 62.99,56.77 C5.1 62.99,55.5 63.68,54.81 63.68,53.06 R5.1
UNNAMED_2_ADILTC7893_I41_TGDN: length 4.3
  TOP w0.254: U1.16 63.99,62.72 64.39,63.12
  TOP w0.508: R21.1 64.39,63.12
UNNAMED_2_ADILTC7893_I41_TGUP: length 5.7
  TOP w0.254: U1.17 63.49,63.36 63.63,63.5
  TOP w0.508: R20.1 67.06,64.39 66.76,64.09 arc(66.6,63.98) 66.4,63.94 64.28,63.94 arc(64.09,63.91) 63.92,63.8 63.63,63.5
UNNAMED_2_ADILTC7893_I41_VBIAS: length 7.5
  TOP w0.254: U1.7 63.99,57.55 65.53,56.01 65.66,56.01 65.66,55.8 C7.1 65.79,55.5 66.5,54.79 66.5,53.09 R14.2
UNNAMED_2_ADILTC7893_I41_VFB: length 5.6
  TOP w0.254: U1.21 61.49,62.84 59.56,64.77 58.93,64.77 58.29,65.41 C2.1
UNNAMED_2_ADILTC7893_I41_VPRG: length 7
  TOP w0.254: R26.1 65.1,53.09 65.1,54.79 64.39,55.5 R27.1 64.39,56.26 63.49,57.16 U1.6
UNNAMED_2_CN6PODDEVEN_I38_N3: length 2.5
  TOP w0.254: JP1.3 15.67,46.26 R10.2
UNNAMED_2_CNTP1P_I3_N1: length 10.6
  TOP w0.254: R3.1 15.16,60.33 TP3.1
UNNAMED_2_CNTP1P_I33_N1: length 4.3
  TOP w0.254: R4.1 TP4.1
UNNAMED_2_IND_I124_N1: length 57.8
  TOP w0.254: R33.1 v1(51.56,64.26)
  LAYER_4 w0.254: v1(51.56,64.26) 52.45,63.37 52.45,52.58 63.5,41.53 66.42,41.53 72.77,35.18 73.79,35.18 v1(74.17,35.56)
  BOTTOM w0.254: R34.1 v1(74.17,35.56)
  BOTTOM w0.381: R32.1 68.88,46.23 76.26,46.23 77.09,45.4 ; 77.09,45.4 77.1,45.4 L1.1 ; 77.09,45.4 77.09,42.88
UNNAMED_2_RES_I30_N2: length 5.7
  TOP w0.254: S1.1 14.81,76.83 R8.2
  BOTTOM w0.254: S1.4 S1.1
VOUT: length 178.5
  TOP w0.381: R35.2 v1(6.48,28.83)
  LAYER_3 w0.254: v1(56.39,72.26) 59.31,75.18 133.73,75.18 133.99,74.93 v1(133.99,74.42)
  LAYER_4 w0.254: v1(6.48,28.83) 63.88,28.83 66.36,31.31 75.5,31.31 80.77,36.58 v1(80.77,56.64)
  BOTTOM w0.254: R37.2 v1(56.39,72.26)
  vias: v1(80.14,72.9) v1(80.64,72.9) v1(80.77,71.25) v1(80.77,70.1) v1(80.77,68.83) v1(80.77,67.69) v1(80.77,65.53) v1(80.77,65.02) v1(80.77,64.52) v1(80.77,62.67) v1(80.77,62.17) v1(80.77,60.71) v1(80.77,60.2) v1(80.77,57.66) v1(80.77,57.15) v1(82.04,71.25) v1(82.04,70.1) v1(82.04,68.83) v1(82.04,67.69) v1(82.55,71.75) v1(83.06,71.75) v1(83.31,71.25) v1(83.31,70.1) v1(83.31,68.83) v1(83.31,67.69) v1(83.57,71.75) v1(84.58,71.25) v1(84.58,70.1) v1(84.58,68.83) v1(84.58,67.69) v1(85.85,71.75) v1(86.36,71.75) v1(86.36,63.88) v1(86.36,62.1) v1(86.87,71.75) v1(88.01,62.99) v1(89.15,71.75) v1(89.66,71.75) v1(89.66,63.88) v1(89.66,62.1) v1(90.17,71.75) v1(91.31,62.99) v1(92.96,63.88) v1(92.96,62.1) v1(94.61,62.99) v1(127.51,67.94) v1(129.29,72.52) v1(129.54,63.12) v1(133.99,61.47) v1(138.56,63.25) v1(138.94,72.26) v1(140.46,67.94) v2(109.73,60.83) v2(109.73,59.05) v2(109.73,57.28) v2(112.52,60.83) v2(112.52,59.05) v2(112.52,57.28) v2(121.16,60.83) v2(121.16,59.05) v2(121.16,57.28) v2(123.95,60.83) v2(123.95,59.05) v2(123.95,57.28) v2(133.22,58.93) v2(133.99,58.93) v2(134.75,58.93) v3(74.95,64.29) v3(74.95,62.84) v3(75.95,64.29) v3(75.95,62.84) v3(76.95,64.29) v3(76.95,62.84)
VSOP: length 2.1
  TOP w0.254: C1.1 56.44,67.74 v1(56.39,67.69) 56.34,67.74 R1.1
  BOTTOM w0.254: R37.1 v1(56.39,67.69)

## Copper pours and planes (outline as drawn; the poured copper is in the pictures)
GND_SIGNAL on TOP: 1.27,1.27 1.27,118.11 142.24,118.11 142.24,1.27 ; 2 cut-outs
GND_SIGNAL on BOTTOM: 1.27,118.11 142.24,118.11 142.24,1.27 1.27,1.27
GND_SIGNAL on LAYER_2: 1.27,118.11 142.24,118.11 142.24,1.27 1.27,1.27
GND_SIGNAL on LAYER_3: 1.27,118.11 1.27,1.27 142.24,1.27 142.24,118.11
GND_SIGNAL on LAYER_4, LAYER_5: 1.27,1.27 1.27,118.11 142.24,118.11 142.24,1.27
VIN on TOP: 65.28,51.44 65.28,49.91 66.29,49.91 66.29,51.44
VIN on TOP: 71.12,33.02 70.48,32.38 70.48,16.51 58.04,16.51 57.78,16.26 57.78,2.92 58.04,2.67 88.65,2.67 88.9,2.92 88.9,32.77 88.65,33.02
VIN on TOP: 14.22,75.69 14.22,74.17 15.24,74.17 15.24,75.69
VIN on TOP: 51.31,62.48 52.96,62.48 52.96,63.5 51.31,63.5
VIN on BOTTOM: 69.85,16.51 58.04,16.51 57.78,16.26 57.78,2.79 58.04,2.54 88.65,2.54 88.9,2.79 88.9,34.29 88.39,34.8 74.68,34.8 74.68,34.04 73.66,34.04 73.66,34.8 70.48,34.8 70.48,17.14
BG on TOP: 68.58,60.07 69.72,60.07 69.72,60.96 69.6,61.09 68.58,61.09
BG on TOP: 74.55,58.99 74.55,59.94 73.98,60.52 71.95,60.52 71.5,60.07 71.5,57.78 72.64,57.78 73.03,58.17 73.03,58.61 73.41,58.99
BG on TOP: 68.58,61.34 69.72,61.34 69.72,62.36 68.58,62.36
BOOST on BOTTOM: 65.66,63.5 65.66,62.23 65.15,61.72 65.15,60.26 66.17,60.26 66.17,61.47 66.93,62.23 66.93,63.5
EXTVCC on TOP: 6.99,25.91 6.99,27.18 3.17,27.18 3.17,25.91
EXTVCC on TOP: 67.06,57.02 68.33,57.02 68.33,58.55 67.06,58.55
INTVCC on TOP: 63.12,68.33 62.87,68.07 62.87,67.06 65.15,67.06 65.15,68.33
INTVCC on TOP: 14.86,48.77 14.86,47.5 15.88,47.5 15.88,48.77
INTVCC on TOP: 66.67,59.05 66.93,58.8 68.33,58.8 68.33,59.82 66.93,59.82 66.67,59.56
INTVCC on TOP: 54.48,55.88 55.75,55.88 55.75,58.17 54.48,58.17
INTVCC on TOP: 66.67,49.91 67.69,49.91 67.69,51.44 66.67,51.44
INTVCC on TOP: 63.88,51.44 63.88,49.91 64.9,49.91 64.9,51.44
INTVCC on TOP: 61.09,51.44 61.09,49.91 62.1,49.91 62.1,51.44
SENSE+ on TOP: 53.34,63.5 53.34,62.36 57.15,62.36 57.15,63.5
SENSE+ on BOTTOM: 67.69,46.48 67.69,45.47 66.04,45.47 66.04,46.48
SENSE- on TOP: 53.47,65.02 53.34,64.9 53.34,63.75 57.15,63.75 57.15,65.02
SENSE- on BOTTOM: 67.18,48.77 67.18,46.74 64.9,46.74 64.9,48.77
SW on TOP: 74.04,72.01 73.66,71.63 73.66,64.45 71.95,64.45 71.5,64.01 71.5,63.37 72.26,62.61 73.53,62.61 73.66,62.48 73.66,59.31 74.8,59.31 74.8,57.78 73.66,56.64 73.66,53.85 73.91,53.59 79.76,53.59 80.01,53.85 80.01,72.01
SW on BOTTOM: 65.41,63.5 65.41,62.36 65.15,62.1 64.14,62.1 64.14,63.5
SW on BOTTOM: 74.04,48.26 79.76,48.26 79.76,56.52 74.04,56.52
SW on BOTTOM: 69.22,48.77 69.22,46.74 67.44,46.74 67.44,48.77
SW on LAYER_2: 72.96,66.17 74.55,64.58 74.55,62.61 72.26,62.61 71.5,63.37 71.5,63.88 71.37,64.01 70.99,64.01 69.6,62.61 65.53,62.61 64.77,61.85 63.37,61.85 63.37,63.63 64.01,64.26 66.55,64.26 67.18,64.9 69.6,64.9 70.87,66.17
SW on LAYER_4: 74.68,61.34 78.23,61.34 79.38,60.2 79.38,53.59 73.66,53.59 73.66,60.33
TG on TOP: 68.58,63.88 69.6,63.88 69.72,64.01 69.72,64.9 68.58,64.9
TG on TOP: 74.55,64.58 74.55,63.69 73.98,63.69 72.9,64.77 71.88,64.77 71.56,65.09 71.56,66.61 71.95,66.99 72.58,66.99 73.15,66.42 73.15,65.98
TG on TOP: 68.58,62.61 69.72,62.61 69.72,63.63 68.58,63.63
UNNAMED_2_ADILTC7893_I41_BGDN on TOP: 67.06,61.34 68.33,61.34 68.33,62.36 67.06,62.36 66.8,62.1 66.8,61.59
UNNAMED_2_ADILTC7893_I41_BGUP on TOP: 67.06,60.07 68.33,60.07 68.33,61.09 67.06,61.09 66.8,60.83 66.8,60.33
UNNAMED_2_ADILTC7893_I41_BSTVCC on BOTTOM: 65.15,59.44 65.15,57.59 66.17,57.59 66.17,59.44
UNNAMED_2_ADILTC7893_I41_DRVCC on TOP: 66.67,52.83 66.67,51.69 67.69,51.69 67.69,52.83
UNNAMED_2_ADILTC7893_I41_DRVCC on TOP: 66.67,56.26 66.67,54.99 67.69,54.99 67.69,56.26
UNNAMED_2_ADILTC7893_I41_DRVSET on TOP: 56.01,57.15 57.28,57.15 57.28,59.44 56.01,59.44
UNNAMED_2_ADILTC7893_I41_DRVUV on TOP: 56.01,54.61 57.28,54.61 57.28,56.9 56.01,56.9
UNNAMED_2_ADILTC7893_I41_DTCA on TOP: 56.01,59.69 57.28,59.69 57.28,60.71 56.01,60.71
UNNAMED_2_ADILTC7893_I41_DTCB on TOP: 56.01,60.96 57.28,60.96 57.28,61.98 56.01,61.98
UNNAMED_2_ADILTC7893_I41_FREQ on TOP: 61.09,56.26 61.09,54.99 62.1,54.99 62.1,56.26
UNNAMED_2_ADILTC7893_I41_FREQ on TOP: 61.09,52.83 61.09,51.69 62.1,51.69 62.1,52.83
UNNAMED_2_ADILTC7893_I41_ILIM on TOP: 63.88,65.53 63.88,66.8 61.59,66.8 61.59,65.53
UNNAMED_2_ADILTC7893_I41_ITH on TOP: 59.05,66.8 59.05,65.53 61.34,65.53 61.34,66.8
UNNAMED_2_ADILTC7893_I41_PGOOD on TOP: 64.14,66.8 64.14,65.28 65.15,65.28 65.15,66.8
UNNAMED_2_ADILTC7893_I41_PLLIN on TOP: 59.69,56.64 59.69,54.99 60.71,54.99 60.71,56.64
UNNAMED_2_ADILTC7893_I41_PLLIN on TOP: 14.99,59.05 14.99,57.66 16,57.66 16,59.05
UNNAMED_2_ADILTC7893_I41_RUN on TOP: 58.29,52.83 58.29,51.69 59.31,51.69 59.31,52.83
UNNAMED_2_ADILTC7893_I41_RUN on TOP: 58.29,56.64 58.29,54.99 59.31,54.99 59.31,56.64
UNNAMED_2_ADILTC7893_I41_SS on TOP: 62.48,56.26 62.48,54.99 63.5,54.99 63.5,56.26
UNNAMED_2_ADILTC7893_I41_SS on TOP: 62.48,52.83 62.48,51.69 63.5,51.69 63.5,52.83
UNNAMED_2_ADILTC7893_I41_TGDN on TOP: 67.06,62.61 68.33,62.61 68.33,63.63 67.06,63.63 66.8,63.37 66.8,62.87
UNNAMED_2_ADILTC7893_I41_TGUP on TOP: 66.8,63.88 68.33,63.88 68.33,64.9 67.18,64.9 66.8,64.52
UNNAMED_2_ADILTC7893_I41_VBIAS on TOP: 65.28,56.26 65.28,54.99 66.29,54.99 66.29,56.26
UNNAMED_2_ADILTC7893_I41_VBIAS on TOP: 65.28,52.83 65.28,51.69 66.29,51.69 66.29,52.83
UNNAMED_2_ADILTC7893_I41_VFB on TOP: 58.8,65.53 58.8,66.8 53.98,66.8 53.98,65.53
UNNAMED_2_ADILTC7893_I41_VPRG on TOP: 63.88,52.83 63.88,51.69 64.9,51.69 64.9,52.83
UNNAMED_2_ADILTC7893_I41_VPRG on TOP: 63.88,56.26 63.88,54.99 64.9,54.99 64.9,56.26
UNNAMED_2_CAP_I18_N2 on TOP: 61.34,69.47 60.33,69.47 60.33,67.06 61.34,67.06
UNNAMED_2_CN6PODDEVEN_I38_N3 on TOP: 14.86,47.24 14.86,45.85 15.88,45.85 15.88,47.24
UNNAMED_2_CNTP1P_I3_N1 on TOP: 14.99,60.58 14.99,59.31 16,59.31 16,60.58
UNNAMED_2_CNTP1P_I33_N1 on TOP: 4.57,29.08 4.57,27.43 5.59,27.43 5.59,29.08
UNNAMED_2_IND_I124_N1 on TOP: 51.31,63.75 52.96,63.75 52.96,64.77 51.31,64.77
UNNAMED_2_IND_I124_N1 on BOTTOM: 70.48,35.18 70.48,44.7 85.09,44.7 85.09,35.18 74.68,35.18 74.68,36.07 73.66,36.07 73.66,35.18
UNNAMED_2_IND_I124_N1 on BOTTOM: 69.09,46.48 69.09,45.47 67.94,45.47 67.94,46.48
UNNAMED_2_RES_I30_N2 on TOP: 14.22,77.34 14.22,75.95 15.24,75.95 15.24,77.34
VOUT on TOP: 85.22,72.01 85.22,66.93 82.55,66.93 82.17,66.55 82.17,55.88 80.26,55.88 80.26,72.01
VOUT on TOP: 5.97,29.08 5.97,27.43 6.99,27.43 6.99,29.08
VOUT on TOP: 140.59,56.39 140.84,56.64 140.84,86.74 140.59,87 127.89,87 127.64,86.74 127.64,74.55 127.38,74.3 108.84,74.3 108.58,74.04 108.58,56.64 108.84,56.39
VOUT on BOTTOM: 55.24,72.52 55.24,70.48 57.53,70.48 57.53,72.52
VOUT on BOTTOM: 74.68,61.34 74.68,74.04 75.06,74.42 127.64,74.42 127.64,86.74 127.89,87 140.72,87 140.97,86.74 140.97,56.26 140.72,56.01 100.84,56.01 95.5,61.34
VOUT on LAYER_3: 74.61,61.59 74.61,74.68 140.97,74.68 140.97,55.88 80.14,55.88 79.63,56.39 79.63,60.33 78.36,61.59
VOUT on LAYER_4: 75.06,66.17 74.68,65.79 74.68,61.59 78.36,61.59 79.63,60.33 79.63,56.39 79.88,56.13 81.79,56.13 82.04,56.39 82.04,65.91 81.79,66.17
VSOP on TOP: 57.53,67.06 57.53,68.33 55.24,68.33 55.24,67.06
VSOP on BOTTOM: 55.24,69.34 55.24,67.31 57.53,67.31 57.53,69.34

Small or netless copper shapes (teardrops, artwork), in the pictures only: 13 on TOP, 16 on BOTTOM, 24 on LAYER_3, 13 on LAYER_4

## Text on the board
User.Comments: D2 (DNI) SOLDER MASK REMOVED | JP1 SHUNT POSITION: FCM (PINS 1-2) | S1 SWITCH POSITION: ON | JP2 SHUNT POSITION: DISABLE SS (PINS 3-4)
Ref Des/Silkscreen Top: * | SEE TABLE BELOW | VIN | 8V | 12V | 24V | 36V | MAX LOAD | 3.5A | 5.5A | 11A | 18A | CONTROLLER WITH GaN FETs | HIGH FREQUENCY, STEP-UP | EVAL-LTC7893-AZ
DIMENSION: FAB NOTES REVISION: 2ND NOVEMBER 2022 | 8.   IMPEDANCE REQUIREMENTS: IF NO STACKUP IS DEFINED, THE VENDOR IS ALLOWED TO ADJUST THE DIELECTRIC | 13.  PLATING SPECIFICATION: | 9.   FILLET OPTIONS TO ENHANCE RELIABILITY AT PAD JUNCTIONS WHERE SPACING PERMITS. | 10.  THIEVING: | 11.  LAYER TO LAYER REGISTRATION SHALL BE WITHIN 0.003 INCHES. | 12.  DRILL SIZES ARE FINISHED HOLE SIZES. ALL HOLES SHALL BE LOCATED WITHIN 0.005 INCHES DTP,UNLESS SPECIFIED. | 14.  SURFACE FINISH: | 15.  SOLDERMASK: | 1.   DIMENSIONS ARE IN INCHES (EXCEPT WHERE NOTED). | ALL DOCUMENTS & SPECIFICATIONS REFERRED TO BELOW SHOULD BE THE LATEST REVISIONS. | 2.  BOARD MATERIAL:(USE CHECKED ITEMS) | 3.   ALL LAMINATES & BONDING MATERIALS SHOULD BE SELECTED FROM IPC-4101 OR IPC-4103,(TG>170 DEGC TD>300 DEGC) | 4.   REFER TO IPC-6010 SERIES, CLASS 2 FOR FABRICATION. | 5.   REFER TO LAMINATION DIAGRAM FOR OVERALL BOARD THICKNESS, TOLERANCE APPLIES AFTER ALL LAMINATION AND PLATING | 6.   BOW & TWIST NOT TO EXCEED 0.0075 INCHES (0.75%) PER LINEAR INCH AND SHOULD BE MEASURED PER IPC-TM-650, METHOD 2.4.22. | 7.   ACCEPTABILITY PER ADI SPECIFICATION TST00115. | 16.  APPLY SILKSCREEN TO BOTH SIDES USING A NON-CONDUCTIVE, EPOXY BASED INK PER ARTWORK. | ( ) FILLETS ALLOWED | (X) FILLETS NOT ALLOWED | ( ) VENDOR MAY ADD THIEVING TO COMPENSATE FOR LOW COPPER DENSITY AREAS MAINTAINING A MINIMUM | (X) VENDOR MAY NOT ADD THIEVING TO COMPENSATE FOR LOW COPPER DENSITY AREAS. | (X) LPI | ( ) OTHER_________ | COLOR | ( ) GREEN | (X) OTHER_________ | (X) WHITE | ( ) OTHER | HINDER PROPER SOLDER WICKING. BARREL RELIEF ON SOLDERMASK ALLOWED IN UNFILLED VIA IN PAD HOLES. | (X) REFER TO LAMINATION DIAGRAM FOR FINISHED COPPER WEIGHT/THICKNESS REQUIRMENTS | (X) IMMERSION GOLD (ENIG) 1.58-3.94 MICRO INCHES OVER 118-236 MICRO INCHES MIN. OF ELECTROLESS NICKEL PER IPC-4552 | ( ) OSP (ORGANIC SOLDERABILITY PRESERVATIVE) | ( ) IMMERSION SILVER | ( ) SOFT WIRE BONDABLE GOLD 30-50 MICRO INCHES OF SOFT WIRE | ( ) EDGE CONNECTOR FINGERS ARE TO BE PLATED WITH 100 MICRO-INCHES(.0001") OF LOW STRESS | THICKNESS & TRACE WIDTHS TO MEET THE IMPEDANCE REQUIREMENT. IF SPECIFIED, THE VENDOR MUST | TRACE WIDTH & SPACING THAT IMPACT THE REQUIREMENTS MUST HAVE WRITTEN APPROVAL FROM ADI. | MINIMUM BARREL PLATING OF 0.001 INCHES. PLATED HOLES SHALL NOT BE ROUGH OR IRREGULAR SO AS TO | SOLDERMASK OVER BARE COPPER OR BARE GOLD (BOTH SIDES) TO MEET IPC-SM-840. | IF PRESENT,DO NOT MODIFY SOLDERMASK DEFINED PADS (MASK OPENINGS LESS THAN COPPER PAD) WITHOUT APPROVAL. | MEET THE REQUIREMENTS LISTED IN THE IMPEDANCE TABLE. ANY ADJUSTMENT MADE TO THE DEFINED STACKUP, | PROCESSES. FINISHED THICKNESS MEASURED FROM TOP COPPER TO BOTTOM COPPER. | (X)  ISOLA 370HR OR S1000-2 OR IT180 OR EQUIVALENT | ( )  ISOLA-FR408HR OR EQUIVALENT | ( )  ISOLA IS410 | ( )  MEGTRON 6 | ( )  NELCO-4000-13 | ( )  ROGERS 4350B | ( )  ROGERS 3003 | ( )  ARLON 85N | ( )  EM370D | ( )  OTHER ________________________ | UL FLAMMABILITY RATING 94V-0. BOARD MATERIAL & CONSTRUCTION SHALL MEET THE REQUIREMENTS OF UL796/UL796F. | BONDABLE GOLD OVER 100-150 MICRO INCHES OF NICKEL | NICKEL UNDER 30 MICRO-INCHES (.0003') OF GOLD | 0.100 INCH CLEARANCE FROM ALL COPPER FEATURES, | THE STARTING COPPER WEIGHT/THICKNESS CAN VARY AS LONG AS THE FINISHED COPPER | WEIGHT/THICKNESS IS NOT LESS THAN THE SPECIFIED VALUE. | UNLESS OTHERWISE SPECIFIED | HOMOGENOUS MATERIALS IN THIS BOARD SHALL BE COMPLAINT WITH THE EU DIRECTIVE 2002/95/EC | BLUE | WORKMANSHIP SHALL CONFORM TO IPC-A-600, CLASS 2. | 21.  INTENTIONAL SHORTS: | 17.  FINAL ELECTRICAL TEST TO BE PERFORMED USING PROVIDED IPC-D-356A NETLIST OR ODB++ FORMAT FILE. | 22.  PEMNUTS: | 23.  MANUFACTURER TO ETCH/STAMP WITH PERMANENT NON-CONDUCTIVE INK | ON SECONDARY SIDE UNLESS OTHERWISE SPECIFIED: | 18.  A TIME DOMAIN REFLECTOMETER REPORT (TDR) FOR EACH IMPEDANCE CONTROLLED LAYER & A CERTIFICATE | 19.  IF PRESENT, ALL BLIND/BURIED VIAS WITH AN ASPECT RATIO <1:1 TO BE PLATED SHUT WITH COPPER WHEN | 20.  FOR VIA FILL INFORMATION REFER TO DRILL CHART: | 25. PANELIZATION: | 27.  MINIMUM DESIGN LINE WIDTH IS .006 INCH. | 28.  MINIMUM DESIGN LINE SPACING IS .006 INCH. | IS ACCEPTABLE, ALL OTHER INSTANCES MUST BE REPORTED. | IF AN INTENTIONAL SHORT REPORT IS SUPPLIED AND DOES NOT MATCH THE FAB DATA THEN | THE PCB SHALL HAVE A VERIFICATION STAMP. | ( )  NON-CONDUCTIVE EPOXY FILL ALL 0.XXXX INCHES DRILLED VIAS | ( )  COPPER FILL ALL 0.XXXX INCHES DRILLED VIAS | ( ) PEMNUTS TO BE INSTALLED BY FABRICATOR | ( ) PEMNUTS NOT TO BE INSTALLED BY FABRICATOR | (X) NOT APPLICABLE | USED AS VIA-IN-PAD OR AS A STACKED VIA. BLIND/BURIED VIAS WITH AN ASPECT RATIO >1:1 TO BE FILLED | A. UL CODE-FLAMMABILITY RATING FOR THOSE APPROVED MATERIALS(IF APPLICABLE) | B. DATE CODE | C. LOT NUMBER | D. MANUFACTURER LOGO | BOARDS TO BE SHIPPED IN ARRAY AND KEPT INTACT | PANEL TO BE SUBJECTED TO CUSTOMERS APPROVAL | PANEL SOLDER PASTE STENCIL GERBER TO BE PROVIDED TO ANALOG | CAN'T BE PERFORMED BECAUSE THE TRACE LENGTH IS TOO SHORT ON THE OUTER LAYERS AT THE PIN ESCAPES | ADI APPROVAL IS REQUIRED. | OF COMPLIANCE SHALL BE PROVIDED BY VENDOR AT TIME OF SHIPMENT. INSTANCES WHERE TDR TESTING | WITH NON-CONDUCTIVE EPOXY. | TOOLING: | FINISH: | NOTES: | MATERIAL: | TESTING: | MISCELLANEOUS: | "0"
User.24: SUPPLY | POWER | VPG | IN | OUT | I | V | LOAD | A | - | +
User.45: FIGURE | SIZE | 6.0 | 10.0 | 12.0 | 35.0 | 36.5 | 100.0 | 200.0 | 118.0 | 187.0 | PLATED | NON-PLATED | FINISHED HOLES IN MILS | ALL UNITS ARE IN MILS | QTY | 28 | 262 | 66 | 18 | 4 | 11 | TOLERANCE/NOTES
